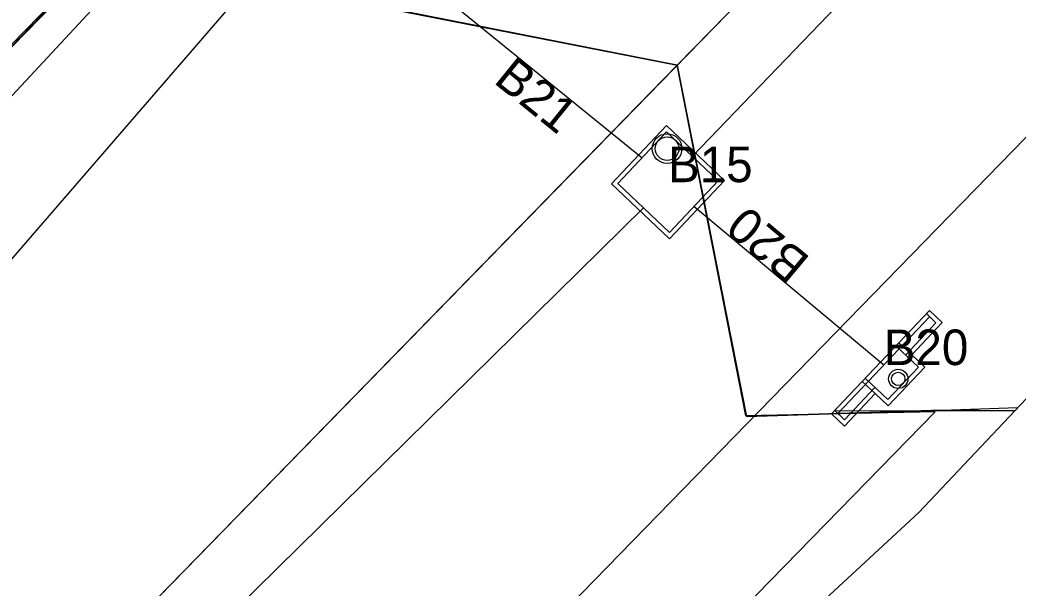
# Model space of a CAD drawing. Extents: x 2253035 to 2279930, y 13774972 to 13793443.
# Drawn here: x 2255711 to 2255823.2, y 13791613 to 13791676.9 of the extents above; entities that cross this region are included whole.
import ezdxf

# ---------------------------------------------------------------- set-up
doc = ezdxf.new("R2010")
doc.units = 0
for name, color, linetype in [('E_Utility_ATT_Fiber', 7, 'Continuous'), ('E_Utility_ATT_Xbox', 7, 'Continuous'), ('E_Utility_Fiber Optic_Fiber Optic Cable_FOC', 7, 'Continuous'), ('E_Utility_Gas_Gas Line_GL_Description', 7, 'Continuous'), ('E_Utility_Gas_Gas Line_GL_Elevation', 7, 'Continuous'), ('E_Utility_Guy Anchor_GUY_point', 7, 'Continuous'), ('E_Utility_Water_Water Line_WL_Description', 7, 'Continuous'), ('E_Utility_Water_Water Line_WL_Elevation', 7, 'Continuous'), ('E_Utility_Water_Water Valve_WV_Elevation', 7, 'Continuous')]:
    doc.layers.add(name, color=color, linetype=linetype)

msp = doc.modelspace()

# ---------------------------------------------------------------- linework, layer by layer
at = {"layer": 'E_Utility_ATT_Fiber'}
for p, q in [((2255857.62, 13791746.14), (2255784.86, 13791671.82)), ((2255784.86, 13791671.82), (2255857.62, 13791746.14)), ((2255784.86, 13791671.82), (2255744.11, 13791679.79)), ((2255744.11, 13791679.79), (2255784.86, 13791671.82)), ((2255684.4, 13791568.86), (2255784.86, 13791671.82)), ((2255792.63, 13791632.31), (2255784.86, 13791671.82)), ((2255784.86, 13791671.82), (2255792.63, 13791632.31)), ((2255814.61, 13791633.04), (2255823.16, 13791633.32)), ((2255792.63, 13791632.31), (2255814.61, 13791633.04))]:
    msp.add_line(p, q, dxfattribs=at)
for points in [[(2255802.53, 13791633.01), (2255822.82, 13791632.96), (2255967.11, 13791785.49)], [(2255685.97, 13791649.23), (2255689.22, 13791645.98), (2255734.94, 13791695.16)], [(2255734.94, 13791695.16), (2255689.22, 13791645.98), (2255685.97, 13791649.23)], [(2255784.86, 13791671.82), (2255684.4, 13791568.86), (2255684.4, 13791568.86)], [(2255713.03, 13791525.45), (2255751.31, 13791564.64), (2255756.83, 13791570.48), (2255812.01, 13791621.53), (2255822.82, 13791632.96)], [(2255822.82, 13791632.96), (2255814.61, 13791633.04), (2255792.63, 13791632.31)]]:
    msp.add_lwpolyline(points, dxfattribs=at)
at = {"layer": 'E_Utility_ATT_Xbox'}
for p, q in [((2255780.91, 13791661.41), (2255780.91, 13791661.41)), ((2255786.56, 13791661.57), (2255786.56, 13791661.57)), ((2255783.81, 13791658.66), (2255783.81, 13791658.66)), ((2255781.06, 13791655.76), (2255781.06, 13791655.76)), ((2255786.72, 13791655.91), (2255786.72, 13791655.91)), ((2255808.06, 13791638.1), (2255808.06, 13791638.1)), ((2255810.87, 13791638.88), (2255810.87, 13791638.88)), ((2255809.15, 13791637.07), (2255809.15, 13791637.07)), ((2255810.24, 13791636.03), (2255810.24, 13791636.03)), ((2255807.44, 13791635.25), (2255807.44, 13791635.25))]:
    msp.add_line(p, q, dxfattribs=at)
at = {"layer": 'E_Utility_Fiber Optic_Fiber Optic Cable_FOC'}
for p, q in [((2255777.45, 13791658.49), (2255783.64, 13791665.02)), ((2255783.64, 13791665.02), (2255790.17, 13791658.84)), ((2255778.16, 13791658.5), (2255783.66, 13791664.32)), ((2255783.66, 13791664.32), (2255789.47, 13791658.82)), ((2255783.99, 13791652.3), (2255777.45, 13791658.49)), ((2255783.97, 13791653.01), (2255778.16, 13791658.5)), ((2255789.47, 13791658.82), (2255783.97, 13791653.01)), ((2255790.17, 13791658.84), (2255783.99, 13791652.3)), ((2255813.2, 13791644.25), (2255802.2, 13791632.63)), ((2255813.22, 13791643.54), (2255802.91, 13791632.65)), ((2255813.94, 13791642.86), (2255812.86, 13791643.89)), ((2255814.65, 13791642.88), (2255813.2, 13791644.25)), ((2255813.94, 13791642.86), (2255810.51, 13791639.23)), ((2255814.65, 13791642.88), (2255811.22, 13791639.24)), ((2255811.96, 13791637.85), (2255809.42, 13791640.26)), ((2255811.22, 13791639.24), (2255809.76, 13791640.62)), ((2255812.67, 13791637.87), (2255811.22, 13791639.24)), ((2255811.96, 13791637.85), (2255808.53, 13791634.22)), ((2255812.67, 13791637.87), (2255808.55, 13791633.51)), ((2255807.07, 13791635.59), (2255803.64, 13791631.96)), ((2255807.09, 13791634.89), (2255805.64, 13791636.26)), ((2255808.53, 13791634.22), (2255805.98, 13791636.62)), ((2255807.09, 13791634.89), (2255803.66, 13791631.25)), ((2255808.55, 13791633.51), (2255807.09, 13791634.89)), ((2255803.66, 13791631.25), (2255802.2, 13791632.63)), ((2255803.64, 13791631.96), (2255802.55, 13791632.99))]:
    msp.add_line(p, q, dxfattribs=at)
for centre, radius in [((2255783.71, 13791662.43), 1.67), ((2255783.71, 13791662.43), 1.33), ((2255809.7, 13791636.55), 1.08), ((2255809.7, 13791636.55), 0.75)]:
    msp.add_circle(centre, radius, dxfattribs=at)
at = {"layer": 'E_Utility_Gas_Gas Line_GL_Description'}
for p, q in [((2255925.63, 13791806.4), (2255786.56, 13791661.57)), ((2255752.28, 13791684.63), (2255780.91, 13791661.41)), ((2255781.06, 13791655.76), (2255674.96, 13791551.42)), ((2255808.06, 13791638.1), (2255786.72, 13791655.91))]:
    msp.add_line(p, q, dxfattribs=at)
at = {"layer": 'E_Utility_Guy Anchor_GUY_point'}
for points in [[(2255743.97, 13791679.92), (2255744.18, 13791709.09), (2255737.22, 13791701.96), (2255743.07, 13791696.22), (2255738.56, 13791691.61), (2255732.69, 13791697.37), (2255686.09, 13791649.27), (2255653.85, 13791683.47), (2255639.34, 13791669.27), (2255679.28, 13791629.46), (2255687.18, 13791621.59), (2255646.31, 13791579.7), (2255631.16, 13791559.16), (2255672.15, 13791556.3), (2255774.99, 13791661.7), (2255784.86, 13791671.82)], [(2255676.02, 13791515.4), (2255699.82, 13791516.12), (2255813.84, 13791632.86), (2255792.56, 13791632.38), (2255784.86, 13791671.82), (2255672.15, 13791556.3)]]:
    msp.add_lwpolyline(points, close=True, dxfattribs=at)
at = {"layer": 'E_Utility_Water_Water Line_WL_Description'}
msp.add_lwpolyline([(2255639.34, 13791669.27), (2255653.79, 13791683.4), (2255685.97, 13791649.23), (2255732.82, 13791697.24), (2255738.56, 13791691.61), (2255743.07, 13791696.22), (2255737.36, 13791701.89), (2255744.29, 13791708.99), (2255744.17, 13791689.55), (2255703.67, 13791642.74), (2255697.78, 13791633.76), (2255677.57, 13791613.04), (2255684.45, 13791625.27)], close=True, dxfattribs=at)
at = {"layer": 'E_Utility_Water_Water Line_WL_Elevation'}
msp.add_lwpolyline([(2255552.69, 13792209.6), (2255414.64, 13792056.03), (2255343.69, 13791984.84), (2255605.99, 13791701.86), (2255609.85, 13791705.81), (2255620.44, 13791716), (2255687.16, 13791650.79), (2255732.69, 13791697.37), (2255738.56, 13791691.61), (2255743.07, 13791696.22), (2255737.22, 13791701.96), (2255882.44, 13791850.6), (2255952.2, 13791922.14), (2256017.05, 13791988.64), (2256050.99, 13792008.43), (2256083.27, 13792042.75), (2256102.42, 13792056.55), (2256121.52, 13792085.4), (2256170.83, 13792144.18)], dxfattribs=at)
msp.add_lwpolyline([(2255888.46, 13791833.54), (2255895.06, 13791863.54), (2255737.22, 13791701.96), (2255743.07, 13791696.22), (2255738.56, 13791691.61), (2255732.69, 13791697.37), (2255687.16, 13791650.79), (2255620.44, 13791716), (2255529.19, 13791619.16), (2255654.52, 13791602.43), (2255648.22, 13791595.97), (2255641.92, 13791570.19), (2255680.31, 13791564.67), (2255857.51, 13791746.27), (2255934.02, 13791825.55)], close=True, dxfattribs=at)
at = {"layer": 'E_Utility_Water_Water Valve_WV_Elevation'}
msp.add_lwpolyline([(2255390.98, 13791330.06), (2255459.85, 13791397.22), (2255383.32, 13791459.9), (2255493.57, 13791567.11), (2255547.29, 13791645.62), (2255605.99, 13791701.86), (2255343.69, 13791984.84), (2255414.64, 13792056.03), (2255552.69, 13792209.6), (2256003.03, 13792697.26), (2256274.85, 13792371.04), (2256429.6, 13792200.7), (2256502.73, 13792117.35), (2256310.07, 13791948.12), (2256237.1, 13792031.76), (2256159.74, 13792001.95), (2256121.45, 13791961.04), (2255952.32, 13791795.31), (2255623, 13791457.45), (2255517, 13791344.43)], dxfattribs=at)

# ---------------------------------------------------------------- texts
at = {"layer": 'E_Utility_Gas_Gas Line_GL_Elevation'}
for s, rotation, p in [('B21', 320.9541, (2255764.08, 13791669.91)), ('B20', 140.1481, (2255799.95, 13791650.08))]:
    msp.add_text(s, height=4, rotation=rotation, dxfattribs=at).set_placement(p)
for s, p in [('B15', (2255783.81, 13791658.66)), ('B20', (2255808.06, 13791638.1))]:
    msp.add_text(s, height=4, dxfattribs=at).set_placement(p)

doc.saveas('drawing.dxf')
